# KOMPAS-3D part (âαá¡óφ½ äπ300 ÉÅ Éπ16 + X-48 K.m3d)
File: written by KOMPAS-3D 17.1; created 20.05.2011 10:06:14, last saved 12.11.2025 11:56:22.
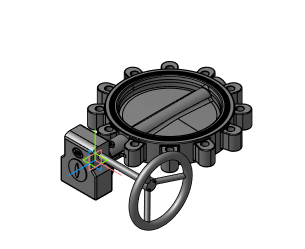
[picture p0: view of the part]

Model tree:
1. Плоскость XY
2. Плоскость ZX
3. Плоскость ZY
4. Ось X
5. Ось Y
6. Ось Z
7. Начало координат
8. Операция без истории:5

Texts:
  Viktor2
